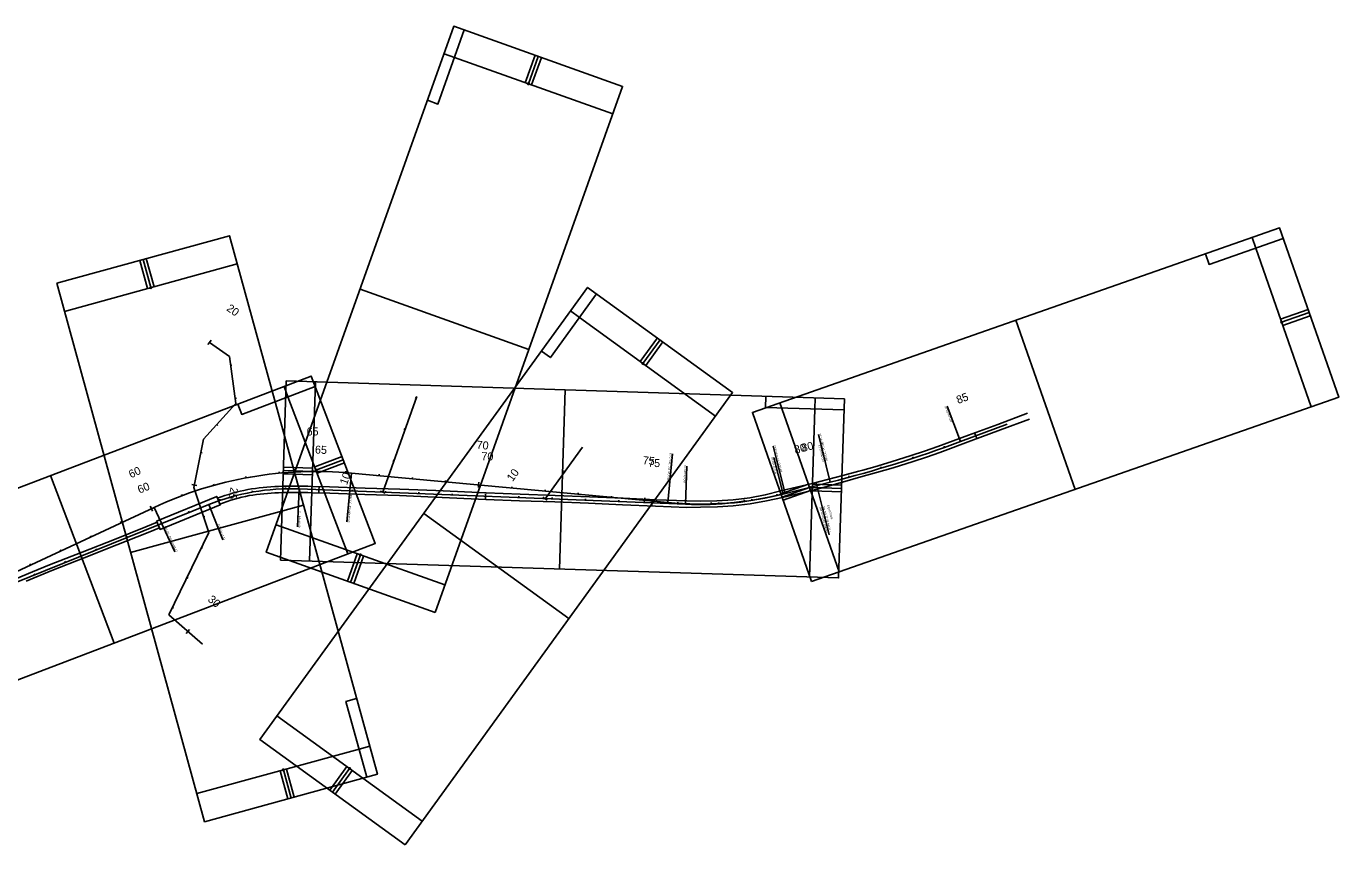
# Model space of a CAD drawing. Extents: x 1965190 to 1971239, y 1116641 to 1119319.
# Drawn here: x 1967302 to 1971239, y 1116864 to 1119319 of the extents above; entities that cross this region are included whole.
import ezdxf

# ---------------------------------------------------------------- set-up
doc = ezdxf.new("R2010")
doc.units = 0
for name, color, linetype in [('RD_EX_Bridge', 7, 'Continuous'), ('RD_EX_Road', 7, 'Continuous'), ('RD_HC_Cl', 7, 'Continuous'), ('RD_HC_CL_Rel', 7, 'Continuous'), ('RD_HC_Data', 7, 'Continuous'), ('RD_HC_Data_Rel', 7, 'Continuous'), ('RD_HC_Data_Tic', 7, 'Continuous'), ('RD_HC_Data_Tic_Rel', 7, 'Continuous'), ('RD_HC_TX_Rel_Sta50', 7, 'Continuous'), ('RD_HC_TX_Sta50', 7, 'Continuous'), ('RD_SHT_Bndy', 7, 'Continuous'), ('RD_SHT_Misc3', 7, 'Continuous')]:
    doc.layers.add(name, color=color, linetype=linetype)

msp = doc.modelspace()

# ---------------------------------------------------------------- linework, layer by layer
at = {"layer": 'RD_EX_Bridge'}
msp.add_lwpolyline([(1967693.2, 1117834.7), (1967873.6, 1117908.4), (1967884, 1117883.1), (1967703.5, 1117809.4), (1967693.2, 1117834.7)], dxfattribs=at)
at = {"layer": 'RD_EX_Road'}
for points in [[(1969956, 1118031.2), (1969996, 1118044.6), (1970036.1, 1118058.4), (1970128.5, 1118091.9), (1970215.9, 1118124.3), (1970305.1, 1118158)], [(1969962.3, 1118013), (1970001.8, 1118026.3), (1970042.5, 1118040.4), (1970135.4, 1118074.7), (1970224, 1118107.7), (1970311.2, 1118140.2)], [(1969282.9, 1117875.4), (1969323.9, 1117876.1), (1969374.9, 1117877.1), (1969422.8, 1117880.6), (1969473.4, 1117886.6), (1969522.6, 1117895.5), (1969570.2, 1117905.2), (1969616.1, 1117916.1), (1969665.8, 1117928.6), (1969710.9, 1117940.6), (1969757.1, 1117953.2), (1969805.3, 1117966.7), (1969852.3, 1117979.8), (1969901.9, 1117994.1), (1969962.3, 1118013)], [(1969810.8, 1117987.5), (1969847, 1117997.6), (1969895.7, 1118011.9), (1969956, 1118031.2)], [(1969283.3, 1117895.4), (1969325.6, 1117894.4), (1969373.8, 1117895.6), (1969422.2, 1117898.6), (1969472.1, 1117904.7), (1969518.5, 1117913.1), (1969565.2, 1117925.2), (1969612.4, 1117936.1), (1969659.1, 1117947.3), (1969705.6, 1117959), (1969751.6, 1117971.4), (1969799.2, 1117984.2), (1969810.8, 1117987.5)], [(1968158.7, 1117938.6), (1968212.1, 1117937.2), (1968318.8, 1117933.3), (1968422.8, 1117929.9), (1968530.5, 1117925.7)], [(1967879, 1117895.5), (1967875.7, 1117903.5)], [(1967879, 1117895.5), (1967883.1, 1117885.6)], [(1968159.2, 1117919.4), (1968212.5, 1117918), (1968317.5, 1117914.4), (1968421.5, 1117910.8), (1968527.8, 1117906.4)], [(1968527.8, 1117906.4), (1968680.8, 1117899.1), (1968781.7, 1117895.4), (1968887.9, 1117891.8), (1968988.7, 1117888.2), (1969090.1, 1117882.8), (1969189.3, 1117879), (1969282.9, 1117875.4)], [(1968530.5, 1117925.7), (1968682, 1117919), (1968783.2, 1117915.4), (1968888.6, 1117911.4), (1968991.2, 1117907.1), (1969092, 1117903.1), (1969191.1, 1117898.7), (1969283.3, 1117895.4)], [(1966769.5, 1117457.5), (1966870.2, 1117497.3), (1966971.2, 1117539), (1967071.1, 1117580.2), (1967172.6, 1117621.5), (1967270.8, 1117661.7), (1967321.1, 1117682.6), (1967371.5, 1117702.9), (1967470.3, 1117741.6), (1967566.7, 1117779.5), (1967661.2, 1117817.5), (1967694.4, 1117831.2), (1967697.9, 1117822.8)], [(1967302.2, 1117654.1), (1967379.3, 1117686.2), (1967476.1, 1117724.4), (1967573.9, 1117763.5), (1967667.7, 1117800.7), (1967701.6, 1117814), (1967697.9, 1117822.8)]]:
    msp.add_lwpolyline(points, dxfattribs=at)
for centre, radius, start, end in [((1968104.9, 1117261.1), 682.1, 101.7162, 109.6396), ((1968075.1, 1117320.6), 617.9, 91.4965, 100.1295), ((1968111.4, 1116608.6), 1330.8, 87.9632, 92.259), ((1968080.6, 1117363), 558.7, 101.3479, 110.7006), ((1968080.7, 1117246.5), 673.3, 91.837, 99.4057), ((1968107.6, 1116504.3), 1416, 87.9115, 91.9598)]:
    msp.add_arc(centre, radius, start, end, dxfattribs=at)
at = {"layer": 'RD_HC_Cl'}
for p, q in [((1967851.7, 1118370.2), (1967911.4, 1118327.7)), ((1967911.4, 1118327.7), (1967931.1, 1118187.5)), ((1968371.4, 1117921), (1968474, 1118208.6)), ((1967931.1, 1118187.5), (1967834, 1118080)), ((1970104, 1118072.9), (1970243.8, 1118125.1)), ((1967834, 1118080), (1967804.8, 1117934.9)), ((1968858.2, 1117901.7), (1968970.1, 1118056.2)), ((1967804.8, 1117934.9), (1967849.8, 1117800.6)), ((1968120.3, 1117930.9), (1969279, 1117884.9)), ((1969571.8, 1117915.4), (1969713.7, 1117951.2)), ((1966770.7, 1117448.1), (1967849.5, 1117883.9)), ((1967849.8, 1117800.6), (1967729.3, 1117553.7)), ((1967729.3, 1117553.7), (1967830.8, 1117465.4))]:
    msp.add_line(p, q, dxfattribs=at)
for centre, radius, start, end in [((1968809, 1121539.8), 3700.9, 284.1493, 290.4823), ((1968094.4, 1117277.5), 653.9, 87.7266, 111.9958), ((1969319.9, 1118914.5), 1030.4, 267.7266, 284.1493)]:
    msp.add_arc(centre, radius, start, end, dxfattribs=at)
at = {"layer": 'RD_HC_CL_Rel'}
for p, q in [((1968277.4, 1117978.5), (1969226.4, 1117889.9)), ((1966858.9, 1117489.3), (1967685.7, 1117875.7))]:
    msp.add_line(p, q, dxfattribs=at)
for centre, radius, start, end in [((1968170.8, 1116837.5), 1145.9, 84.6661, 115.0463), ((1969323.3, 1118927.1), 1041.7, 264.6661, 284.1493)]:
    msp.add_arc(centre, radius, start, end, dxfattribs=at)
at = {"layer": 'RD_HC_Data'}
for p, q in [((1970104, 1118072.9), (1970064.3, 1118179.2)), ((1969713.7, 1117951.2), (1969685.9, 1118061.4)), ((1969571.8, 1117915.4), (1969544, 1118025.5)), ((1969279, 1117884.9), (1969283.5, 1117998.9)), ((1968120.3, 1117930.9), (1968115.8, 1117817.5)), ((1967849.5, 1117883.9), (1967891.9, 1117778.7))]:
    msp.add_line(p, q, dxfattribs=at)
at = {"layer": 'RD_HC_Data_Rel'}
for p, q in [((1969713.7, 1117951.2), (1969677.8, 1118093.7)), ((1969577.9, 1117916.9), (1969542, 1118059.3)), ((1969226.4, 1117889.9), (1969240.1, 1118036.2)), ((1968277.4, 1117978.5), (1968263.7, 1117832.3)), ((1969673.3, 1117941), (1969710.4, 1117793.7)), ((1967685.7, 1117875.7), (1967748.1, 1117742.2))]:
    msp.add_line(p, q, dxfattribs=at)
at = {"layer": 'RD_HC_Data_Tic'}
for p, q in [((1967851.7, 1118370.2), (1967847.1, 1118363.7)), ((1967851.7, 1118370.2), (1967856.4, 1118376.7)), ((1967915.1, 1118301.2), (1967919, 1118301.7)), ((1968472.1, 1118203.5), (1968468.4, 1118204.9)), ((1967929, 1118202.2), (1967933, 1118202.7)), ((1967874, 1118124.2), (1967876.9, 1118121.6)), ((1968438.5, 1118109.4), (1968434.8, 1118110.7)), ((1970150.1, 1118090.1), (1970147.3, 1118097.6)), ((1970150.1, 1118090.1), (1970152.9, 1118082.6)), ((1970056.3, 1118055.4), (1970055, 1118059.2)), ((1967826.1, 1118040.4), (1967830, 1118039.6)), ((1968404.9, 1118015.2), (1968401.2, 1118016.5)), ((1969961.7, 1118023), (1969960.5, 1118026.8)), ((1968916.8, 1117982.6), (1968913.6, 1117985)), ((1969770.1, 1117965.9), (1969769.1, 1117969.7)), ((1969866.3, 1117993.1), (1969865.2, 1117997)), ((1967806.3, 1117942.4), (1967798.5, 1117943.9)), ((1967806.3, 1117942.4), (1967814.2, 1117940.8)), ((1968079.9, 1117931.3), (1968079.8, 1117935.3)), ((1968179.9, 1117928.6), (1968180.2, 1117936.6)), ((1969673.3, 1117941), (1969671.3, 1117948.7)), ((1969673.3, 1117941), (1969675.2, 1117933.2)), ((1967883.8, 1117896.6), (1967882.5, 1117900.4)), ((1967980.5, 1117921.5), (1967979.8, 1117925.4)), ((1968179.9, 1117928.6), (1968179.6, 1117920.6)), ((1968279.8, 1117924.6), (1968280, 1117928.6)), ((1968371.4, 1117921), (1968363.8, 1117923.7)), ((1968371.4, 1117921), (1968378.9, 1117918.3)), ((1968379.7, 1117920.6), (1968379.9, 1117924.6)), ((1968479.6, 1117916.7), (1968479.8, 1117920.7)), ((1968579.6, 1117912.7), (1968579.7, 1117916.7)), ((1968679.5, 1117908.7), (1968679.2, 1117900.8)), ((1968679.5, 1117908.7), (1968679.8, 1117916.7)), ((1968779.4, 1117904.8), (1968779.6, 1117908.8)), ((1968858.2, 1117901.7), (1968851.7, 1117906.3)), ((1968858.2, 1117901.7), (1968864.7, 1117897)), ((1968879.3, 1117900.8), (1968879.5, 1117904.8)), ((1968979.3, 1117896.8), (1968979.4, 1117900.8)), ((1969079.2, 1117892.9), (1969079.3, 1117896.9)), ((1969179.1, 1117888.9), (1969179.4, 1117896.9)), ((1969379, 1117885.8), (1969378.7, 1117889.8)), ((1969478.4, 1117896.4), (1969477.8, 1117900.3)), ((1969576.3, 1117916.5), (1969575.3, 1117920.4)), ((1967790.7, 1117860.1), (1967789.2, 1117863.8)), ((1969179.1, 1117888.9), (1969178.8, 1117880.9)), ((1969279, 1117884.9), (1969279.2, 1117888.9)), ((1967698, 1117822.7), (1967695, 1117830.1)), ((1967698, 1117822.7), (1967700.9, 1117815.2)), ((1967834.2, 1117847.3), (1967838, 1117848.6)), ((1967605.2, 1117785.2), (1967603.7, 1117788.9)), ((1967512.5, 1117747.7), (1967511, 1117751.5)), ((1967827.6, 1117755), (1967831.1, 1117753.2)), ((1967419.8, 1117710.3), (1967418.3, 1117714)), ((1967327.1, 1117672.8), (1967325.6, 1117676.5)), ((1967783.7, 1117665.1), (1967787.3, 1117663.4)), ((1967739.8, 1117575.2), (1967743.4, 1117573.5)), ((1967786.6, 1117503.8), (1967781.4, 1117497.8)), ((1967786.6, 1117503.8), (1967791.9, 1117509.8))]:
    msp.add_line(p, q, dxfattribs=at)
at = {"layer": 'RD_HC_Data_Tic_Rel'}
for p, q in [((1968060.9, 1117978.1), (1968060.5, 1117982.1)), ((1968160.7, 1117983.4), (1968160.6, 1117991.4)), ((1968160.7, 1117983.4), (1968160.8, 1117975.4)), ((1968260.6, 1117979.9), (1968260.9, 1117983.9)), ((1968360.2, 1117970.7), (1968360.5, 1117974.7)), ((1967864.5, 1117941.7), (1967863.4, 1117945.6)), ((1967961.9, 1117964.2), (1967961.1, 1117968.1)), ((1968459.7, 1117961.4), (1968460.1, 1117965.4)), ((1968559.3, 1117952.1), (1968559.7, 1117956.1)), ((1968658.9, 1117942.8), (1968658.1, 1117934.9)), ((1968658.9, 1117942.8), (1968659.6, 1117950.8)), ((1968758.4, 1117933.5), (1968758.8, 1117937.5)), ((1969651.4, 1117935.5), (1969649.4, 1117943.2)), ((1969651.4, 1117935.5), (1969653.3, 1117927.7)), ((1969673.3, 1117941), (1969671.3, 1117948.7)), ((1969673.3, 1117941), (1969675.2, 1117933.2)), ((1967769.4, 1117910.8), (1967768, 1117914.6)), ((1968858, 1117924.3), (1968858.4, 1117928.2)), ((1968957.6, 1117915), (1968957.9, 1117918.9)), ((1969057.1, 1117905.7), (1969057.5, 1117909.6)), ((1969156.7, 1117896.4), (1969156, 1117888.4)), ((1969156.7, 1117896.4), (1969157.4, 1117904.3)), ((1969256.3, 1117887.5), (1969256.6, 1117891.5)), ((1969356.3, 1117885.9), (1969356.1, 1117889.9)), ((1969455.9, 1117893.8), (1969455.4, 1117897.8)), ((1969554.3, 1117911.3), (1969553.4, 1117915.2)), ((1967677.4, 1117871.8), (1967674, 1117879)), ((1967677.4, 1117871.8), (1967680.7, 1117864.5)), ((1967586.8, 1117829.4), (1967585.1, 1117833.1)), ((1967496.2, 1117787.1), (1967494.5, 1117790.7)), ((1967405.6, 1117744.8), (1967403.9, 1117748.4)), ((1967315, 1117702.4), (1967313.3, 1117706.1))]:
    msp.add_line(p, q, dxfattribs=at)
at = {"layer": 'RD_SHT_Bndy'}
for p, q in [((1968798.8, 1119149.3), (1968828.2, 1119231.7)), ((1968586.4, 1119225), (1969061.4, 1119055.6)), ((1968817.7, 1119142.5), (1968847.1, 1119224.9)), ((1970989.4, 1118653.2), (1971155.9, 1118177.2)), ((1967934.9, 1118605.9), (1967416.6, 1118463.4)), ((1967642.9, 1118616.4), (1967666.1, 1118532)), ((1967662.2, 1118621.7), (1967685.4, 1118537.3)), ((1968961.1, 1118445.2), (1969369.4, 1118149.3)), ((1971063.9, 1118440.3), (1971146.5, 1118469.2)), ((1971070.5, 1118421.5), (1971153.1, 1118450.4)), ((1969143.7, 1118312.8), (1969195.1, 1118383.7)), ((1969159.9, 1118301.1), (1969211.2, 1118372)), ((1968169.3, 1118252), (1968152, 1117714.8)), ((1968087, 1118207.4), (1968266.9, 1117736.3)), ((1969562.6, 1118189.1), (1969740.1, 1117681.8)), ((1969667.5, 1118170.6), (1969651.3, 1117666.6)), ((1968167.5, 1117996.7), (1968249.2, 1118027.9)), ((1968174.6, 1117978), (1968256.4, 1118009.2)), ((1968072.9, 1117976.2), (1968160.4, 1117973.4)), ((1968073.5, 1117996.2), (1968161, 1117993.4)), ((1969565.5, 1117916), (1969648.1, 1117944.9)), ((1969660.2, 1117945.2), (1969747.7, 1117942.4)), ((1969572.1, 1117897.1), (1969654.7, 1117926)), ((1969659.6, 1117925.2), (1969747, 1117922.4)), ((1968051.2, 1117823.4), (1968557.5, 1117642.8)), ((1968265.5, 1117654), (1968294.9, 1117736.4)), ((1968284.4, 1117647.3), (1968313.7, 1117729.7)), ((1968054.1, 1117249.9), (1968489.4, 1116934.6)), ((1968300.3, 1117150.7), (1967814, 1117017.1)), ((1968063.5, 1117085.6), (1968086.7, 1117001.2)), ((1968082.8, 1117090.9), (1968106, 1117006.5)), ((1968212.3, 1117027.3), (1968263.7, 1117098.1)), ((1968228.5, 1117015.5), (1968279.9, 1117086.4))]:
    msp.add_line(p, q, dxfattribs=at)
for points in [[(1968528.1, 1117560.4), (1969090.8, 1119138), (1968584.5, 1119318.6), (1968021.8, 1117740.9)], [(1967393.4, 1118547.8), (1967837.2, 1116932.7), (1968355.5, 1117075.1), (1967911.7, 1118690.2)], [(1969657.5, 1117652.9), (1971238.5, 1118206.1), (1971061, 1118713.5), (1969480, 1118160.2)], [(1968438.1, 1116863.7), (1969420.8, 1118220.1), (1968985.5, 1118535.5), (1968002.8, 1117179.1)], [(1966783.9, 1117169.9), (1968348.7, 1117767.5), (1968156.9, 1118269.6), (1966592.1, 1117672)], [(1968064.6, 1117717.6), (1969738.7, 1117663.8), (1969756, 1118201), (1968081.9, 1118254.8)]]:
    msp.add_lwpolyline(points, close=True, dxfattribs=at)
for points in [[(1968505.3, 1119096.5), (1968536.6, 1119085.3), (1968615.8, 1119307.4)], [(1970838.4, 1118635.6), (1970849.4, 1118604.2), (1971072, 1118682.1)], [(1968847.1, 1118344.5), (1968874, 1118325), (1969012.4, 1118516)], [(1967936.6, 1118185.5), (1967948.4, 1118154.5), (1968168.7, 1118238.6)], [(1969520.3, 1118208.6), (1969519.2, 1118175.4), (1969754.9, 1118167.8)], [(1968293, 1117302.5), (1968261, 1117293.7), (1968323.5, 1117066.3)]]:
    msp.add_lwpolyline(points, dxfattribs=at)
at = {"layer": 'RD_SHT_Misc3'}
for p, q in [((1968555.1, 1119236.2), (1968586.4, 1119225)), ((1968808.3, 1119145.9), (1968837.6, 1119228.3)), ((1970978.4, 1118684.6), (1970989.4, 1118653.2)), ((1967652.5, 1118619), (1967675.7, 1118534.7)), ((1968303.2, 1118529.8), (1968809.4, 1118349.2)), ((1968934.2, 1118464.6), (1968961.1, 1118445.2)), ((1971067.2, 1118430.9), (1971149.8, 1118459.8)), ((1970270.5, 1118436.8), (1970448, 1117929.5)), ((1969151.8, 1118307), (1969203.1, 1118377.8)), ((1968075.2, 1118238.4), (1968087, 1118207.4)), ((1968918.9, 1118227.9), (1968901.7, 1117690.7)), ((1969668.5, 1118203.8), (1969667.5, 1118170.6)), ((1968171, 1117987.3), (1968252.8, 1118018.6)), ((1967374.5, 1117970.8), (1967566.3, 1117468.7)), ((1968073.2, 1117986.2), (1968160.7, 1117983.4)), ((1969568.8, 1117906.6), (1969651.4, 1117935.5)), ((1969659.9, 1117935.2), (1969747.4, 1117932.4)), ((1968133.6, 1117882.7), (1967615.3, 1117740.3)), ((1968494.2, 1117857.3), (1968929.4, 1117541.9)), ((1968274.9, 1117650.7), (1968304.3, 1117733.1)), ((1968332.3, 1117159.5), (1968300.3, 1117150.7)), ((1968073.2, 1117088.3), (1968096.3, 1117003.9)), ((1968220.4, 1117021.4), (1968271.8, 1117092.2))]:
    msp.add_line(p, q, dxfattribs=at)
for centre in [(1968808.3, 1119145.9), (1967675.7, 1118534.7), (1971067.2, 1118430.9), (1969151.8, 1118307), (1968160.7, 1117983.4), (1968171, 1117987.3), (1969651.4, 1117935.5), (1969659.9, 1117935.2), (1968304.3, 1117733.1), (1968073.2, 1117088.3), (1968271.8, 1117092.2)]:
    msp.add_circle(centre, 2.5, dxfattribs=at)

# ---------------------------------------------------------------- texts
at = {"layer": 'RD_HC_Data'}
for s, rotation, p in [('PT=84+50.80', 110.4823, (1970079.4, 1118133.1)), ('PC=80+41.73', 104.1493, (1969695.9, 1118013.7)), ('PT=78+95.34', 104.1493, (1969553.9, 1117977.9)), ('PC=76+00.00', 87.7266, (1969279.6, 1117950)), ('PT=64+40.40', 267.7266, (1968119.8, 1117865.9)), ('PC=61+63.41', 291.9958, (1967875.7, 1117824.3))]:
    msp.add_text(s, height=6, rotation=rotation, dxfattribs=at).set_placement(p)
at = {"layer": 'RD_HC_Data_Rel'}
for s, rotation, p in [('RELOC. PC=80+41.73', 104.1493, (1969706.1, 1118015.6)), ('RELOC. PT=79+24.27', 104.1493, (1969569.5, 1117982.3)), ('RELOC. PC=75+70.03', 84.6661, (1969230.5, 1117954.8)), ('RELOC. PT=66+16.82', 264.6661, (1968273.3, 1117913.6)), ('Sta 80+00.00 AHEAD', 284.1493, (1969681.4, 1117876)), ('Sta 80+22.58 BACK = ', 284.1493, (1969691.1, 1117878.4)), ('EQUATION:', 284.1493, (1969704.7, 1117881.9)), ('RELOC. PC=60+09.22', 295.0463, (1967715, 1117817.6))]:
    msp.add_text(s, height=6, rotation=rotation, dxfattribs=at).set_placement(p)
at = {"layer": 'RD_HC_TX_Rel_Sta50'}
for s, rotation, p in [('65', 0.5072, (1968143.3, 1118091.2)), ('70', 354.6661, (1968652.1, 1118051.9)), ('80', 14.1493, (1969608.6, 1118036.1)), ('80', 14.1493, (1969630.5, 1118041.6)), ('75', 354.6661, (1969150.4, 1118005.4)), ('60', 25.0463, (1967616.3, 1117962.5))]:
    msp.add_text(s, height=24, rotation=rotation, dxfattribs=at).set_placement(p)
at = {"layer": 'RD_HC_TX_Sta50'}
for s, rotation, p in [('20', 324.4755, (1967900.7, 1118467.9)), ('85', 20.4823, (1970097, 1118185.5)), ('65', 357.7266, (1968167.8, 1118037.1)), ('80', 14.1493, (1969630.5, 1118041.6)), ('70', 357.7266, (1968666.9, 1118017.3)), ('75', 357.7266, (1969167, 1117997.5)), ('10', 70.3698, (1968264, 1117941.3)), ('10', 54.0772, (1968760.8, 1117951.3)), ('60', 21.9958, (1967641.8, 1117916.5)), ('25', 258.6104, (1967915.4, 1117937.1)), ('30', 318.9993, (1967844.7, 1117596.4))]:
    msp.add_text(s, height=24, rotation=rotation, dxfattribs=at).set_placement(p)

doc.saveas('drawing.dxf')
